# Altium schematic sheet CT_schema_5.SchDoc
size 218 x 258 mm
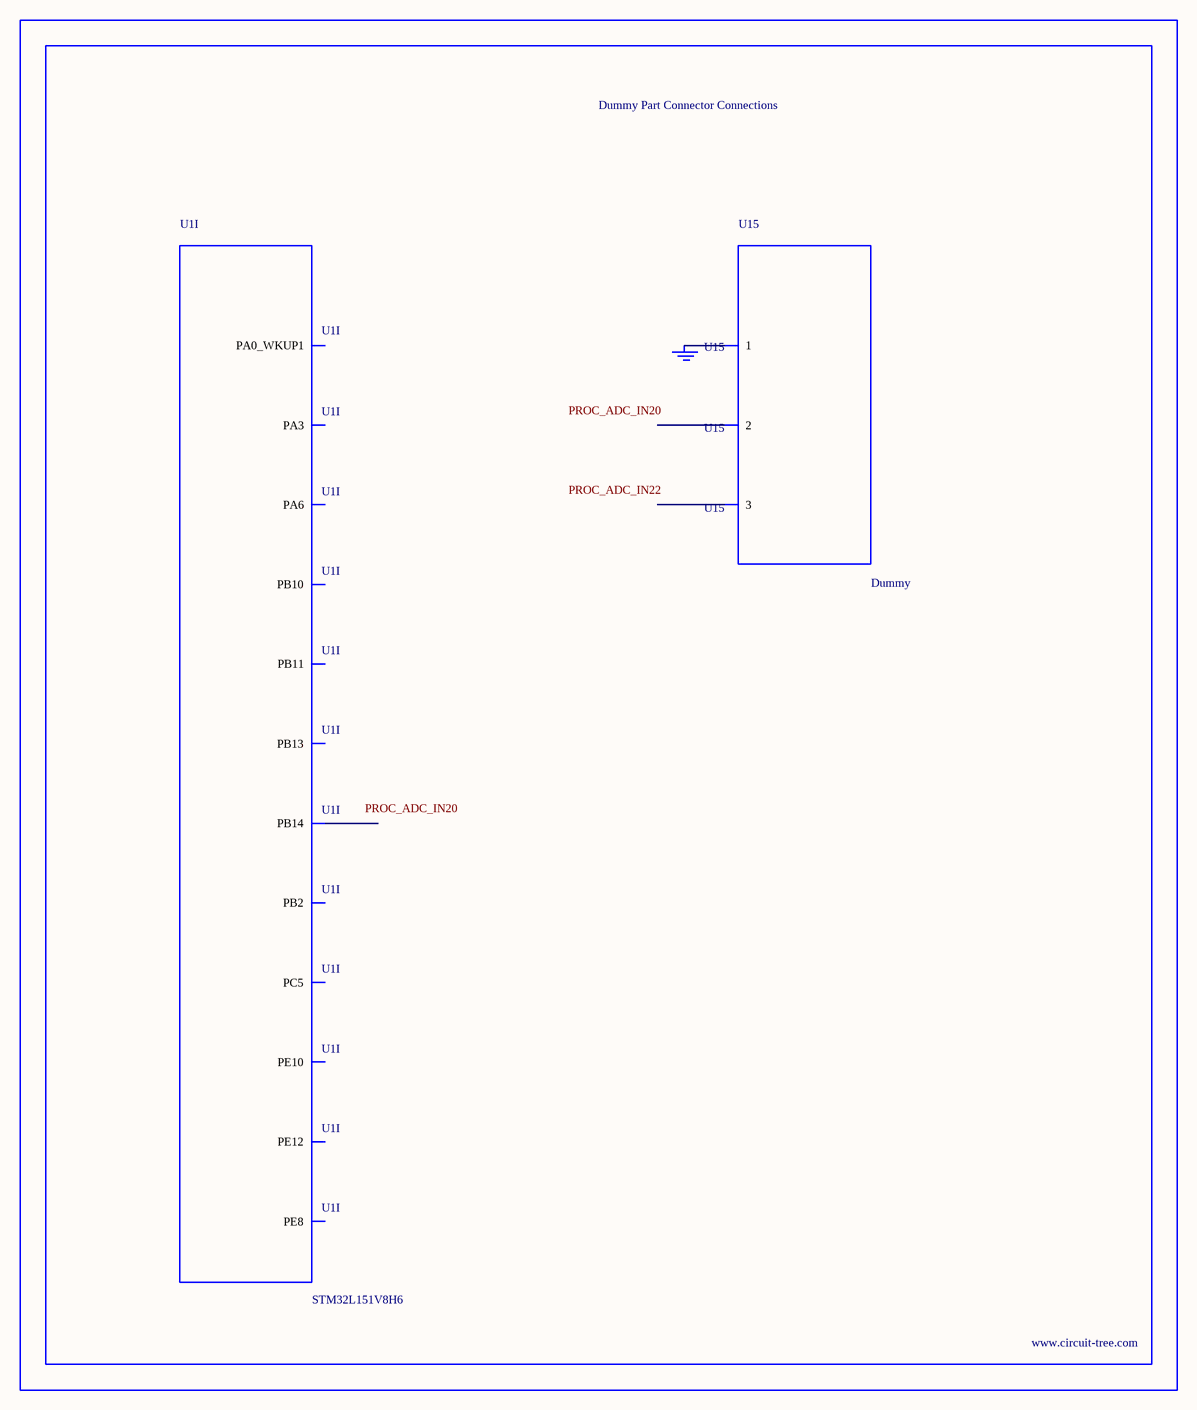
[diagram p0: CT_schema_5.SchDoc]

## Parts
BORDER4  (no value)
GND_INSTANCE_4_0  (no value)
U1  STM32L151V8H6  [UFBGA100]  (part I of 9)
U15  Dummy  [DUMMY_PACKAGE_120]

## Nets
NetGND_INSTANCE_4_0_0: GND_INSTANCE_4_0.0(GND) U15.1

Not connected (* = marked no-connect by the designer): U1 K11(PB14) K12(PB13) L2(PA0_WKUP1) L3(PA3) L4(PA6) L5(PC5) L6(PB2) L7(PE8) L8(PE10) L9(PE12) L10(PB10) L11(PB11); U15 2 3

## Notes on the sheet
- Labels drawn without touching a wire or pin: PROC_ADC_IN20, PROC_ADC_IN22

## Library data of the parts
BORDER4 = BORDER_PAGE4
GND_INSTANCE_4_0 = GND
